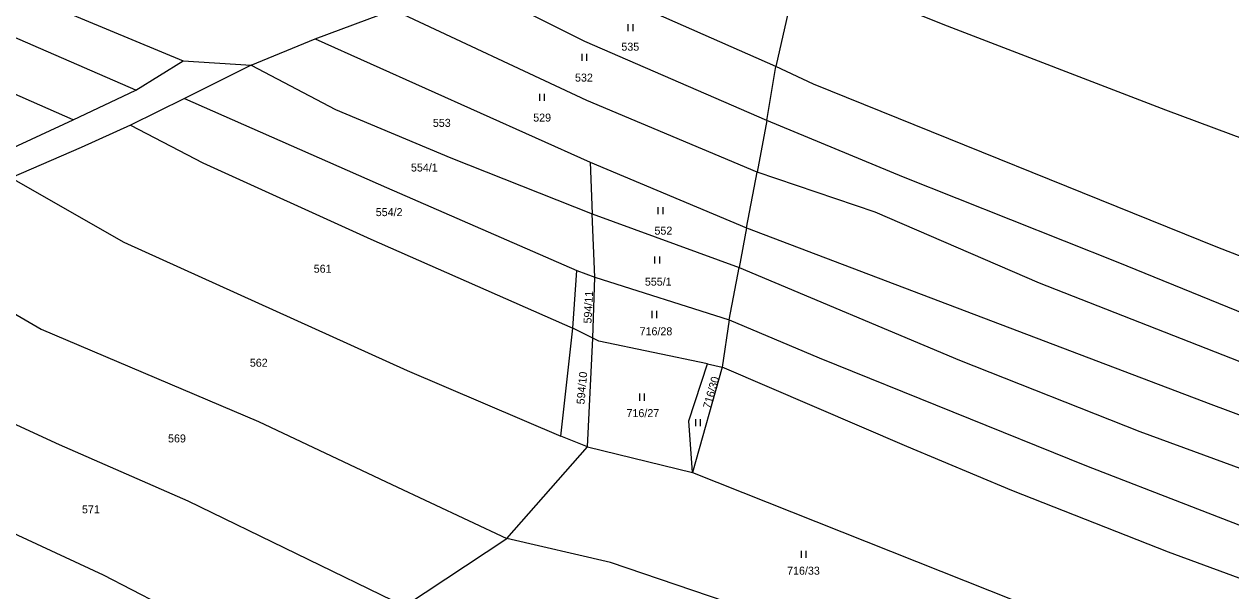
# Model space of a CAD drawing. Extents: x -7483133 to -743169, y -11317770 to -1127091.
# Drawn here: x -748441 to -748184.6, y -1130995.4 to -1130874.9 of the extents above; entities that cross this region are included whole.
import ezdxf

# ---------------------------------------------------------------- set-up
doc = ezdxf.new("R2010")
doc.units = 0
for name, color, linetype in [('Hranice parcel', 7, 'Continuous'), ('Parcelní čísla', 7, 'Continuous'), ('Značky kultur', 7, 'Continuous')]:
    doc.layers.add(name, color=color, linetype=linetype)

msp = doc.modelspace()

# ---------------------------------------------------------------- linework, layer by layer
at = {"layer": 'Hranice parcel'}
for p, q in [((-748276.46, -1130862.6), (-748281.3, -1130883.89)), ((-748281.3, -1130883.89), (-748319.69, -1130866.98)), ((-748379.12, -1130878.04), (-748362.61, -1130871.86)), ((-748392.75, -1130883.62), (-748379.12, -1130878.04)), ((-748379.12, -1130878.04), (-748320.72, -1130904.27)), ((-748417.27, -1130888.93), (-748407.23, -1130882.69)), ((-748407.23, -1130882.69), (-748392.75, -1130883.62)), ((-748392.75, -1130883.62), (-748406.9, -1130890.75)), ((-748283.22, -1130895.4), (-748281.3, -1130883.89)), ((-748430.56, -1130895.23), (-748417.27, -1130888.93)), ((-748406.9, -1130890.75), (-748418.37, -1130896.38)), ((-748444.32, -1130901.6), (-748430.56, -1130895.23)), ((-748283.22, -1130895.4), (-748285.26, -1130906.35)), ((-748320.72, -1130904.27), (-748287.49, -1130918.18)), ((-748320.72, -1130904.27), (-748320.27, -1130915.24)), ((-748287.49, -1130918.18), (-748285.26, -1130906.35)), ((-748320.27, -1130915.24), (-748289.04, -1130926.63)), ((-748319.71, -1130928.71), (-748320.27, -1130915.24)), ((-748287.49, -1130918.18), (-748289.04, -1130926.63)), ((-748324.42, -1130939.55), (-748323.55, -1130927.27)), ((-748323.55, -1130927.27), (-748319.71, -1130928.71)), ((-748291.2, -1130937.79), (-748289.04, -1130926.63)), ((-748320.15, -1130941.67), (-748319.71, -1130928.71)), ((-748319.71, -1130928.71), (-748291.2, -1130937.79)), ((-748326.95, -1130962.5), (-748324.42, -1130939.55)), ((-748320.15, -1130941.67), (-748324.42, -1130939.55)), ((-748291.2, -1130937.79), (-748292.72, -1130947.82)), ((-748321.33, -1130964.79), (-748320.15, -1130941.67)), ((-748292.72, -1130947.82), (-748298.99, -1130970.22)), ((-748295.77, -1130947.1), (-748292.72, -1130947.82)), ((-748321.33, -1130964.79), (-748326.95, -1130962.5)), ((-748338.46, -1130984.21), (-748321.33, -1130964.79)), ((-748321.33, -1130964.79), (-748298.99, -1130970.22)), ((-748360.19, -1130998.63), (-748338.46, -1130984.21))]:
    msp.add_line(p, q, dxfattribs=at)
for points in [[(-748640.02, -1130785.32), (-748543.51, -1130825.81), (-748464.71, -1130858.77), (-748407.23, -1130882.69)], [(-748417.27, -1130888.93), (-748482.75, -1130860.42), (-748530.93, -1130839.89), (-748573.14, -1130821.5), (-748615.5, -1130805.28), (-748644.72, -1130792.86)], [(-748430.56, -1130895.23), (-748489.17, -1130869.4), (-748574.8, -1130833.09), (-748650.5, -1130802.12)], [(-747973.45, -1130994.17), (-747986.3, -1130986.83), (-748025.01, -1130962.88), (-748060.2, -1130946.83), (-748098.9, -1130931.91), (-748130.17, -1130918.61), (-748198.42, -1130893.2), (-748245.75, -1130874.96), (-748272.8, -1130864.07)], [(-748283.22, -1130895.4), (-748321.83, -1130878.64), (-748346.93, -1130865.99)], [(-748285.26, -1130906.35), (-748321.46, -1130891.15), (-748362.61, -1130871.86)], [(-748392.75, -1130883.62), (-748374.81, -1130893.06), (-748350.31, -1130903.3), (-748320.27, -1130915.24)], [(-747988.29, -1131007.37), (-748020.12, -1130990.83), (-748065.85, -1130966.16), (-748067.15, -1130968.63), (-748096.2, -1130958.44), (-748125.51, -1130946.33), (-748187.39, -1130922.39), (-748273.25, -1130887.68), (-748281.3, -1130883.89)], [(-748406.9, -1130890.75), (-748364, -1130909.67), (-748323.55, -1130927.27)], [(-748418.37, -1130896.38), (-748428.88, -1130901.17), (-748443.77, -1130907.57)], [(-748418.37, -1130896.38), (-748403.05, -1130904.37), (-748367.33, -1130920.63), (-748324.42, -1130939.55)], [(-747997.28, -1131017.11), (-748018.68, -1131003.71), (-748045.37, -1130990.45), (-748069.08, -1130977.72), (-748070.08, -1130979.7), (-748099.08, -1130968.76), (-748165.81, -1130943.03), (-748208.52, -1130925.59), (-748254.13, -1130907.42), (-748283.22, -1130895.4)], [(-748004.94, -1131025.41), (-748031.76, -1131008.11), (-748074.61, -1130987.79), (-748075.44, -1130989.47), (-748105.93, -1130976.94), (-748156.11, -1130957.09), (-748225.28, -1130930), (-748260.16, -1130914.87), (-748285.26, -1130906.35)], [(-748443.77, -1130907.57), (-748419.77, -1130921.28), (-748359.61, -1130948.54), (-748326.95, -1130962.5)], [(-748287.49, -1130918.18), (-748188.9, -1130955.67), (-748145.76, -1130971.78), (-748118.89, -1130983.08), (-748080.1, -1130998.3), (-748079.5, -1130997.21), (-748034.8, -1131018.75), (-748011.89, -1131032.94)], [(-748463.91, -1130924.32), (-748437.34, -1130939.73), (-748391.2, -1130959.35), (-748362.89, -1130972.76), (-748338.46, -1130984.21)], [(-748289.04, -1130926.63), (-748242.28, -1130946.35), (-748203.98, -1130961.53), (-748174.74, -1130972.17), (-748148.5, -1130982.18), (-748113.18, -1130996.46), (-748085.2, -1131007.26), (-748084.35, -1131005.87), (-748041.45, -1131026.93), (-748018.5, -1131041.2)], [(-748485.95, -1130936.62), (-748455.56, -1130954.14), (-748433.55, -1130964.26), (-748406.22, -1130976.23), (-748360.19, -1130998.63)], [(-748291.2, -1130937.79), (-748272.09, -1130945.83), (-748215.31, -1130968.76), (-748170.66, -1130986.1), (-748095.78, -1131014.6), (-748071.94, -1131022.78), (-748051.38, -1131033.51), (-748037.07, -1131043.09), (-748025.45, -1131049.82)], [(-748295.77, -1130947.1), (-748318.91, -1130942.31), (-748320.15, -1130941.67)], [(-748512.7, -1130944.65), (-748464.62, -1130973.2), (-748424.22, -1130991.94), (-748412.15, -1130998.16), (-748403.69, -1131002.73), (-748383.15, -1131012.7)], [(-748298.99, -1130970.22), (-748299.79, -1130959.24), (-748295.77, -1130947.1)], [(-748032.6, -1131059.05), (-748050.36, -1131049.71), (-748092.33, -1131027.98), (-748112.55, -1131020.43), (-748157.35, -1131002.56), (-748178.05, -1130994.42), (-748197.86, -1130987.14), (-748231.13, -1130974.02), (-748253.46, -1130964.66), (-748292.72, -1130947.82)], [(-748298.99, -1130970.22), (-748225.2, -1130999.57), (-748204.79, -1131007.48)], [(-748248.56, -1131014.62), (-748284.95, -1131000.02), (-748316.44, -1130989.36), (-748338.46, -1130984.21)]]:
    msp.add_lwpolyline(points, dxfattribs=at)
at = {"layer": 'Značky kultur'}
for p, q in [((-748312.62, -1130876.44), (-748312.62, -1130874.94)), ((-748311.62, -1130876.44), (-748311.62, -1130874.94)), ((-748322.45, -1130882.71), (-748322.45, -1130881.21)), ((-748321.45, -1130882.71), (-748321.45, -1130881.21)), ((-748331.41, -1130891.21), (-748331.41, -1130889.71)), ((-748330.41, -1130891.21), (-748330.41, -1130889.71)), ((-748306.25, -1130915.33), (-748306.25, -1130913.83)), ((-748305.25, -1130915.33), (-748305.25, -1130913.83)), ((-748306.96, -1130925.79), (-748306.96, -1130924.29)), ((-748305.96, -1130925.79), (-748305.96, -1130924.29)), ((-748307.57, -1130937.38), (-748307.57, -1130935.88)), ((-748306.57, -1130937.38), (-748306.57, -1130935.88)), ((-748310.16, -1130954.95), (-748310.16, -1130953.45)), ((-748309.16, -1130954.95), (-748309.16, -1130953.45)), ((-748298.27, -1130960.39), (-748298.27, -1130958.89)), ((-748297.27, -1130960.39), (-748297.27, -1130958.89)), ((-748275.85, -1130988.38), (-748275.85, -1130986.88)), ((-748274.85, -1130988.38), (-748274.85, -1130986.88))]:
    msp.add_line(p, q, dxfattribs=at)

# ---------------------------------------------------------------- texts
at = {"layer": 'Parcelní čísla'}
for s, p in [('535', (-748314.1, -1130880.56)), ('532', (-748323.95, -1130887.13)), ('529', (-748332.83, -1130895.63)), ('553', (-748354.15, -1130896.75)), ('554/1', (-748358.8, -1130906.24)), ('554/2', (-748366.28, -1130915.72)), ('552', (-748307.07, -1130919.66)), ('561', (-748379.46, -1130927.75)), ('555/1', (-748309.11, -1130930.5)), ('716/28', (-748310.23, -1130941.05)), ('562', (-748393.03, -1130947.73)), ('716/27', (-748313.01, -1130958.44)), ('569', (-748410.41, -1130963.82)), ('571', (-748428.69, -1130978.89)), ('716/33', (-748278.89, -1130991.93))]:
    msp.add_text(s, height=1.7, dxfattribs=at).set_placement(p)
for s, rotation, p in [('594/11', 87, (-748320.46, -1130938.58)), ('594/10', 85, (-748321.95, -1130955.79)), ('716/30', 74, (-748295.18, -1130956.79))]:
    msp.add_text(s, height=1.7, rotation=rotation, dxfattribs=at).set_placement(p)

doc.saveas('drawing.dxf')
